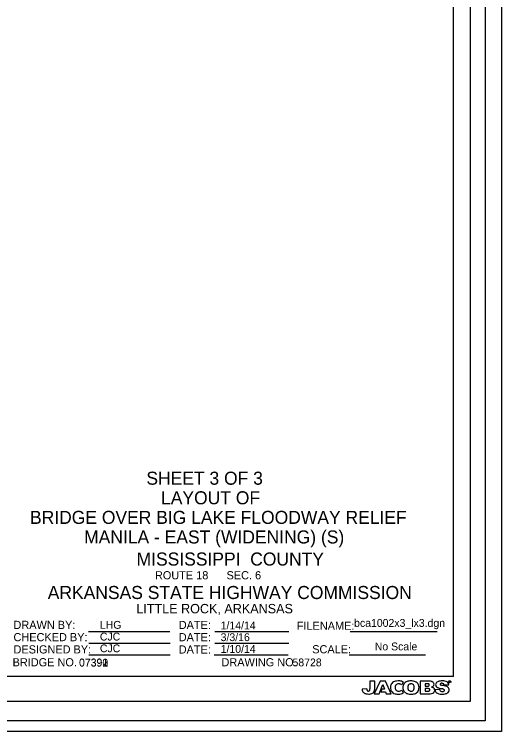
# Model space of a CAD drawing. Extents: x -40 to 1219, y 101 to 761.
# Drawn here: x 770.8 to 994.6, y 101.4 to 431 of the extents above; entities that cross this region are included whole.
import ezdxf

# ---------------------------------------------------------------- set-up
doc = ezdxf.new("R2010")
doc.units = 0
for name, color, linetype in [('border', 7, 'Continuous'), ('Border 2660-Hwy18 - Level 62', 7, 'Continuous'), ('Border 2660-Hwy18 - Level 63', 7, 'Continuous'), ('Border 2660-Hwy18 - Text', 7, 'Continuous'), ('Border 2660-Hwy18 - Title Text', 7, 'Continuous'), ('Bridge No BLFR', 7, 'Continuous'), ('Bridge No BLO', 7, 'Continuous'), ('Bridge No Ditch 81', 7, 'Continuous'), ('Level 62 PDF', 7, 'Continuous'), ('Text', 7, 'Continuous'), ('Title Text', 7, 'Continuous')]:
    doc.layers.add(name, color=color, linetype=linetype)

msp = doc.modelspace()

# ---------------------------------------------------------------- linework, layer by layer
at = {"layer": 'border'}
for p, q in [((972.44, 126.75), (972.44, 743.11)), ((804.82, 147.49), (842.12, 147.49)), ((862.82, 147.45), (896.84, 147.45)), ((924.92, 147.45), (965, 147.45)), ((805.04, 142.09), (842.33, 142.09)), ((862.82, 142.05), (896.84, 142.05)), ((805.04, 136.69), (842.33, 136.69)), ((862.49, 136.65), (896.51, 136.65)), ((924.54, 136.65), (959.51, 136.65)), ((972.44, 126.75), (12.1, 126.75))]:
    msp.add_line(p, q, dxfattribs=at)
for points in [[(936.28, 121.36), (936.28, 124.67), (934.06, 124.67), (934.06, 121.05)], [(939.97, 123.09), (940.75, 120.97), (939.59, 120.97), (939.1, 119.7), (941.21, 119.7), (941.56, 118.73), (943.89, 118.73), (941.2, 124.61), (938.78, 124.61), (936.08, 118.73), (938.35, 118.73), (939.97, 123.09)], [(961.46, 124.61), (957.19, 124.61), (957.19, 118.73)], [(960.4, 123.42), (959.42, 123.42), (959.42, 122.31)], [(959.42, 122.31), (960.46, 122.31)], [(968.14, 122.86), (970.24, 122.96)], [(970.59, 124.54), (970.14, 124.54), (970.14, 124.48), (970.32, 124.48), (970.32, 123.98), (970.4, 123.98), (970.4, 124.48), (970.59, 124.48), (970.59, 124.54)], [(970.73, 124.45), (970.73, 124.45), (970.91, 123.98), (970.97, 123.98), (971.15, 124.45), (971.15, 124.45), (971.15, 123.98), (971.22, 123.98), (971.22, 124.54), (971.12, 124.54), (970.94, 124.07), (970.76, 124.54), (970.66, 124.54), (970.66, 123.98), (970.73, 123.98), (970.73, 124.45)], [(932.63, 121.02), (930.51, 120.91)], [(957.19, 118.73), (961.02, 118.73)], [(960.55, 121.18), (959.42, 121.18), (959.42, 119.99)], [(959.42, 119.99), (960.57, 119.99)], [(966.08, 120.78), (963.97, 120.67)]]:
    msp.add_lwpolyline(points, dxfattribs=at)
for centre, radius, start, end in [((946.43, 121.82), 2.96, 155.2444, 178.6811), ((945.94, 122.05), 2.43, 126.8513, 155.2444), ((946.53, 121.26), 3.41, 94.7853, 126.8513), ((948.78, 121.6), 3.11, 161.2834, 178.6702), ((946.53, 122.36), 0.728, 134.3139, 161.2834), ((947.18, 121.69), 1.67, 110.7655, 134.3139), ((947.15, 113.81), 10.89, 86.903, 94.7853), ((947.15, 121.76), 1.59, 91.5073, 110.7655), ((947.2, 119.88), 3.48, 82.6359, 91.5073), ((947.46, 121.86), 1.48, 65.5548, 82.6359), ((947.56, 121.31), 3.38, 56.9246, 86.903), ((946.6, 119.96), 3.56, 54.6002, 65.5548), ((956.15, 119.35), 8.27, 144.635, 154.8844), ((952.21, 121.74), 3.01, 148.6249, 181.2859), ((951.57, 122.13), 2.26, 123.8806, 148.6249), ((952.69, 120.47), 4.26, 111.7104, 123.8806), ((952.33, 121.38), 3.28, 96.5371, 111.7104), ((954.17, 121.67), 2.75, 160.8611, 181.2981), ((952.38, 122.28), 0.861, 136.1177, 160.8611), ((952.88, 121.8), 1.55, 117.7176, 136.1177), ((953.26, 113.21), 11.51, 91.9058, 96.5371), ((952.69, 122.16), 1.15, 100.2108, 117.7176), ((952.97, 120.65), 2.68, 90.9675, 100.2108), ((953.09, 119.73), 4.98, 73.4477, 92.4253), ((952.93, 121.47), 1.87, 67.077, 90.4218), ((953.21, 122.12), 1.16, 24.6274, 67.077), ((952.74, 121.9), 1.68, 2.7442, 24.6274), ((946.94, 121.63), 7.48, 0.0845, 2.7442), ((953.55, 121.29), 3.36, 41.1934, 73.4477), ((954.78, 122.36), 1.74, 18.6966, 41.1934), ((952.71, 121.66), 3.91, 344.5708, 18.6966), ((960.36, 119.37), 4.05, 86.2098, 89.3498), ((960.46, 124.21), 1.9, 270.0363, 284.1438), ((960.52, 121.87), 1.54, 74.8723, 86.2098), ((960.78, 122.94), 0.589, 284.1438, 307.8865), ((960.77, 122.8), 0.588, 40.2425, 74.8723), ((960.86, 122.83), 0.447, 307.8866, 341.4625), ((960.97, 122.97), 0.324, 21.9604, 40.2425), ((960.73, 122.87), 0.584, 341.4625, 21.9604), ((961.46, 121.5), 3.11, 72.1885, 90.1477), ((961.75, 124.05), 2.26, 284.6785, 296.8411), ((961.86, 122.74), 1.81, 61.4844, 72.1885), ((961.91, 122.84), 1.69, 34.7868, 61.4844), ((962.13, 123.29), 1.41, 296.8412, 329.8182), ((962.53, 123.27), 0.944, 16.9455, 34.7868), ((962.56, 123.05), 0.922, 329.8182, 347.0949), ((962.12, 123.14), 1.37, 347.0949, 16.9455), ((965.48, 122.97), 1.25, 177.6485, 218.8535), ((965.66, 122.96), 1.43, 124.08, 177.6485), ((965.83, 123.25), 1.7, 218.8535, 233.6549), ((966.6, 121.58), 3.1, 108.2808, 124.08), ((966.39, 122.21), 2.43, 99.8173, 108.2808), ((967.22, 117.44), 7.27, 93.402, 99.8173), ((966.52, 123.16), 0.245, 165.3108, 208.2887), ((966.75, 123.1), 0.479, 146.4706, 165.3108), ((966.74, 123.31), 0.506, 211.7417, 226.6339), ((966.57, 123.22), 0.263, 130.7855, 146.4706), ((966.69, 123.26), 0.435, 226.6339, 245.1429), ((966.9, 122.84), 0.767, 97.3055, 130.7855), ((967.2, 124.36), 1.65, 245.1429, 260.9806), ((967.24, 117.1), 7.62, 80.6549, 93.402), ((967.07, 121.54), 2.08, 81.3212, 97.3055), ((964.69, 108.53), 14.38, 77.5139, 80.9806), ((967.22, 122.53), 1.08, 57.474, 81.3212), ((967.47, 122.93), 0.606, 37.1977, 57.474), ((954.97, 64.66), 59.32, 76.8035, 77.5139), ((967.11, 122.66), 1.05, 11.0051, 37.1977), ((968.04, 121.96), 2.69, 57.5906, 80.6549), ((967.4, 117.65), 4.89, 65.6998, 76.8035), ((968.45, 119.98), 2.33, 51.3565, 65.6998), ((968.68, 122.98), 1.48, 39.0736, 57.5906), ((968.41, 122.75), 1.84, 6.4385, 39.0736), ((934.17, 121.2), 3.68, 184.5698, 198.1069), ((932.18, 120.54), 1.58, 198.1069, 225.9799), ((932.74, 121.13), 2.39, 225.9799, 261.0714), ((933.5, 126), 7.32, 261.0714, 269.9405), ((934.45, 120.96), 1.81, 178.2556, 191.4961), ((933.49, 120.76), 0.83, 191.4961, 218.7511), ((933.22, 120.55), 0.491, 218.7511, 257.488), ((933.34, 121.08), 1.03, 257.488, 275.7834), ((933.37, 120.82), 0.771, 275.7834, 301.6926), ((933.5, 123.69), 5.01, 269.9405, 279.1616), ((933.58, 120.48), 0.367, 301.6926, 325.4171), ((933.18, 120.75), 0.855, 325.4171, 349.1575), ((931.68, 121.04), 2.38, 349.1575, 360), ((933.86, 121.5), 2.79, 279.1616, 305.8646), ((934.46, 120.66), 1.76, 305.8646, 338.7843), ((934.63, 120.6), 1.58, 338.7843, 350.0951), ((919.95, 123.16), 16.47, 350.0951, 351.3706), ((932.57, 121.24), 3.71, 351.3706, 1.8291), ((948.06, 121.79), 4.6, 178.6811, 194.3912), ((945.3, 121.08), 1.75, 194.3912, 214.1799), ((947, 122.23), 3.8, 214.1799, 231.6615), ((946.07, 121.05), 2.3, 231.6616, 258.686), ((947.37, 127.57), 8.94, 258.686, 268.8163), ((948.23, 121.61), 2.56, 178.6702, 195.8531), ((946.98, 121.25), 1.26, 195.8531, 214.5369), ((946.9, 121.2), 1.16, 214.5369, 253.1918), ((947.23, 122.29), 2.31, 253.1918, 291.1956), ((947.28, 123), 4.37, 268.8163, 299.3878), ((947.06, 122.74), 2.78, 291.1956, 305.5144), ((959.57, 125.95), 12.2, 206.7197, 213.678), ((953.77, 121.78), 4.57, 181.2859, 193.1956), ((951.32, 121.2), 2.05, 193.1956, 217.7499), ((952.33, 121.99), 3.33, 217.7499, 244.1703), ((952, 121.31), 2.58, 244.1703, 259.4942), ((954.27, 121.67), 2.85, 181.2981, 197.9492), ((953.17, 127.61), 8.98, 259.4942, 268.6426), ((952.41, 121.06), 0.897, 197.9492, 222.7741), ((952.79, 121.42), 1.42, 222.7741, 250.1955), ((952.83, 121.51), 1.52, 250.1955, 269.1264), ((952.89, 125.73), 5.73, 269.1264, 272.0424), ((953.08, 124.03), 5.4, 268.6426, 285.9017), ((953.04, 121.53), 1.54, 272.0424, 299.5401), ((953.27, 121.13), 1.08, 299.5401, 342.4003), ((951.69, 121.63), 2.73, 342.4003, 0.0845), ((953.74, 121.73), 3.02, 285.9017, 322.6714), ((954.47, 121.18), 2.09, 322.6714, 344.5708), ((960.41, 113.78), 7.41, 86.6838, 88.8756), ((960.56, 123.11), 3.12, 270.0001, 276.6749), ((960.75, 119.69), 1.49, 75.9314, 86.6838), ((960.77, 121.3), 1.29, 276.6749, 293.0645), ((960.71, 128.87), 10.14, 271.7224, 279.6279), ((960.87, 120.18), 0.985, 59.6202, 75.9314), ((961.07, 120.6), 0.535, 293.0645, 337.5037), ((961.14, 120.64), 0.45, 30.8341, 59.6202), ((961.07, 120.6), 0.53, 337.5037, 30.8341), ((961.84, 119.15), 2.76, 61.0815, 79.9242), ((962.1, 120.67), 1.83, 279.6279, 313.6357), ((962.61, 120.54), 1.17, 44.9773, 61.0815), ((962.31, 120.46), 1.53, 313.6357, 342.9845), ((962.48, 120.41), 1.35, 342.9845, 44.9773), ((975.25, 122.26), 11.4, 187.9971, 189.0947), ((965.49, 120.7), 1.51, 189.0947, 202.464), ((966.53, 121.13), 2.64, 202.464, 215.8926), ((965.9, 120.67), 1.86, 215.8926, 243.2968), ((966.24, 123.81), 2.39, 233.6549, 244.7689), ((966.29, 121.43), 2.71, 243.2968, 257.4598), ((967.22, 125.88), 4.69, 244.7689, 253.473), ((967.08, 125.02), 6.39, 257.4598, 268.8656), ((968.65, 130.69), 9.7, 253.473, 259.8297), ((967.62, 121.02), 1.57, 188.5141, 201.638), ((967.06, 120.79), 0.957, 201.638, 242.3635), ((967.24, 121.14), 1.35, 242.3635, 264.6229), ((965.37, 112.38), 8.9, 76.0104, 79.8297), ((967.34, 122.2), 2.42, 264.6229, 273.901), ((967.41, 121.18), 1.39, 273.901, 289.1925), ((966.81, 118.18), 2.92, 67.9593, 76.0104), ((967.46, 123.95), 5.32, 270.7612, 282.5001), ((967.61, 120.61), 0.79, 289.1925, 322.566), ((967.61, 120.15), 0.795, 39.9313, 67.9593), ((967.88, 120.39), 0.434, 2.1813, 39.9313), ((967.9, 120.39), 0.422, 322.566, 2.1813), ((967.91, 121.95), 3.27, 282.5001, 295.6144), ((968.32, 121.09), 2.32, 295.6144, 314.022), ((968.92, 120.58), 1.57, 36.5162, 51.3565), ((968.66, 120.74), 1.82, 314.022, 345.1611), ((969.01, 120.64), 1.46, 345.1611, 36.5162), ((967.3, 136.06), 17.43, 268.8656, 270.7612)]:
    msp.add_arc(centre, radius, start, end, dxfattribs=at)
at = {"layer": 'Border 2660-Hwy18 - Level 62'}
msp.add_lwpolyline([(-36.5, 760.68), (987.05, 760.68), (987.05, 106.39), (-36.5, 106.39)], close=True, dxfattribs=at)
at = {"layer": 'Border 2660-Hwy18 - Level 63'}
msp.add_lwpolyline([(-39.83, 756.39), (980.15, 756.39), (980.15, 115.31), (-39.83, 115.31)], close=True, dxfattribs=at)
at = {"layer": 'Level 62 PDF'}
msp.add_lwpolyline([(-29, 755.68), (994.55, 755.68), (994.55, 101.39), (-29, 101.39)], close=True, dxfattribs=at)

# ---------------------------------------------------------------- texts
at = {"layer": 'Border 2660-Hwy18 - Text'}
for s, p in [('DRAWN BY:', (770.37, 148.58)), ('DATE:', (846.26, 148.55)), ('FILENAME:', (900.47, 148.19)), ('CHECKED BY:', (770.37, 142.96)), ('DATE:', (846.26, 142.93)), ('DESIGNED BY:', (770.37, 137.33)), ('DATE:', (846.26, 137.3)), ('SCALE:', (907.56, 137.39)), ('BRIDGE NO.', (769.96, 131.4)), ('DRAWING NO.', (865.89, 131.41))]:
    msp.add_text(s, height=3.75, dxfattribs=at).set_placement(p)
at = {"layer": 'Border 2660-Hwy18 - Title Text'}
for s, height, p in [('MISSISSIPPI  COUNTY', 6, (826.91, 177.72)), ('ROUTE 18      SEC. 6', 3.75, (835.33, 171.39)), ('ARKANSAS STATE HIGHWAY COMMISSION', 6, (786.1, 162.34)), ('LITTLE ROCK, ARKANSAS', 4.32, (826.78, 155.77))]:
    msp.add_text(s, height=height, dxfattribs=at).set_placement(p)
at = {"layer": 'Bridge No BLFR'}
msp.add_text('07392', height=3.6, dxfattribs=at).set_placement((800.47, 131.27))
at = {"layer": 'Bridge No BLO'}
msp.add_text('07391', height=3.6, dxfattribs=at).set_placement((800.47, 131.41))
at = {"layer": 'Bridge No Ditch 81'}
msp.add_text('07390', height=3.6, dxfattribs=at).set_placement((800.47, 131.27))
at = {"layer": 'Text'}
for s, p in [('LHG', (810.04, 148.68)), ('1/14/14', (865.51, 148.4)), ('bca1002x3_lx3.dgn', (926.8, 149.55)), ('CJC', (810.04, 143.28)), ('3/3/16', (865.51, 143)), ('No Scale', (936.29, 138.75)), ('CJC', (810.04, 137.88)), ('1/10/14', (865.51, 137.6)), ('58728', (898.5, 131.41))]:
    msp.add_text(s, height=3.6, dxfattribs=at).set_placement(p)
at = {"layer": 'Title Text'}
for s, p in [('SHEET 3 OF 3', (831.4, 214.87)), ('LAYOUT OF', (838.14, 205.87)), ('BRIDGE OVER BIG LAKE FLOODWAY RELIEF', (777.95, 196.87)), ('MANILA - EAST (WIDENING) (S)', (802.8, 187.87))]:
    msp.add_text(s, height=6, dxfattribs=at).set_placement(p)

doc.saveas('drawing.dxf')
